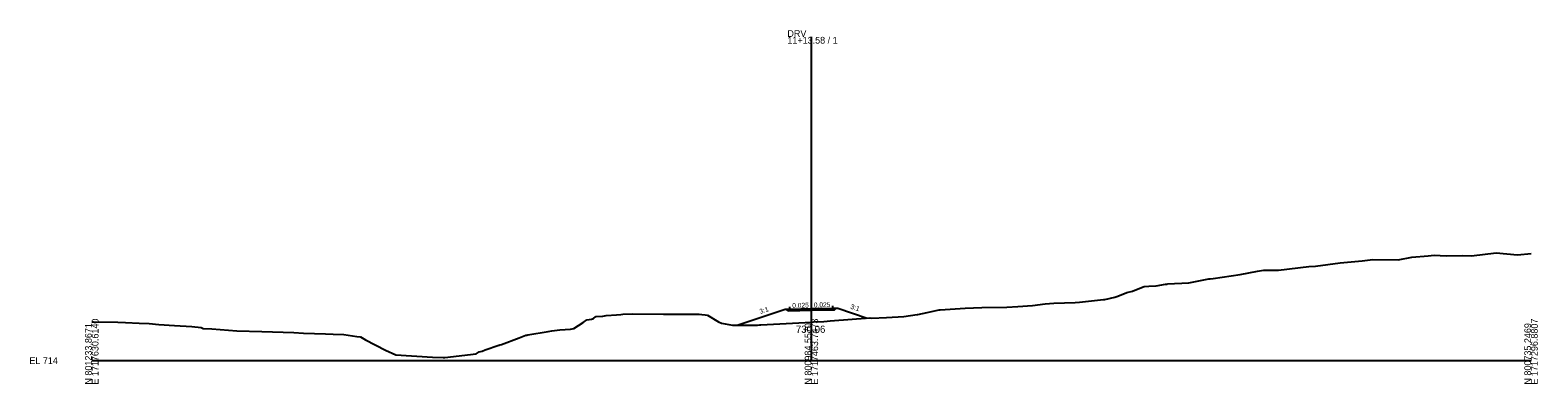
# Model space of a CAD drawing. Extents: x -26 to 603, y -10 to 3134.
# Drawn here: x -26 to 603, y 2490 to 2638 of the extents above; entities that cross this region are included whole.
import ezdxf

# ---------------------------------------------------------------- set-up
doc = ezdxf.new("R2010")
doc.units = 0
for name, color, linetype in [('Exist Cross Section Cell', 7, 'Continuous'), ('Exist XS Center Line Elevation Label', 7, 'Continuous'), ('Exist XS Ground Line', 7, 'Continuous'), ('Prop XS Dump Level', 7, 'Continuous'), ('Prop XS EOT Tick Mark', 7, 'Continuous'), ('Prop XS Finish Grade', 7, 'Continuous'), ('Prop XS Finish Grade Earthwork', 7, 'Continuous'), ('Prop XS Finish Grade Pavement', 7, 'Continuous'), ('Prop XS Pvmt Edge Slope', 7, 'Continuous'), ('Prop XS SE Text', 7, 'Continuous'), ('Prop XS Side Slope Text', 7, 'Continuous'), ('Prop XS Subgrade Earthwork', 7, 'Continuous')]:
    doc.layers.add(name, color=color, linetype=linetype)

msp = doc.modelspace()

# ---------------------------------------------------------------- linework, layer by layer
at = {"layer": 'Exist Cross Section Cell'}
for p, q in [((300, 2500), (300, 2634.89)), ((0, 2500), (300, 2500)), ((300, 2500), (600, 2500))]:
    msp.add_line(p, q, dxfattribs=at)
at = {"layer": 'Exist XS Ground Line'}
for p, q in [((507.41, 2539.22), (510.16, 2539.36)), ((510.16, 2539.36), (520.41, 2540.77)), ((520.41, 2540.77), (529.59, 2541.6)), ((529.59, 2541.6), (534, 2542.06)), ((534, 2542.06), (544.58, 2542)), ((544.58, 2542), (550.25, 2543.15)), ((550.25, 2543.15), (557.13, 2543.67)), ((557.13, 2543.67), (559.61, 2543.86)), ((559.61, 2543.86), (564.63, 2543.59)), ((564.63, 2543.59), (571.59, 2543.8)), ((571.59, 2543.8), (575.2, 2543.65)), ((575.2, 2543.65), (585.45, 2544.96)), ((585.45, 2544.96), (594.35, 2544.04)), ((594.35, 2544.04), (600, 2544.64)), ((457.39, 2532.36), (465.74, 2534.01)), ((465.74, 2534.01), (466.24, 2534.08)), ((466.24, 2534.08), (467.54, 2534.2)), ((467.54, 2534.2), (478.72, 2535.82)), ((478.72, 2535.82), (486, 2537.32)), ((486, 2537.32), (488.5, 2537.69)), ((488.5, 2537.69), (494.73, 2537.65)), ((494.73, 2537.65), (507.41, 2539.22)), ((426.47, 2526.43), (427.71, 2526.91)), ((427.71, 2526.91), (431.5, 2528.3)), ((431.5, 2528.3), (433.89, 2528.88)), ((433.89, 2528.88), (438.36, 2530.69)), ((438.36, 2530.69), (438.74, 2530.82)), ((438.74, 2530.82), (438.92, 2530.84)), ((438.92, 2530.84), (440.67, 2531.05)), ((440.67, 2531.05), (443.66, 2531.13)), ((443.66, 2531.13), (447.63, 2531.85)), ((447.63, 2531.85), (448.24, 2531.91)), ((448.24, 2531.91), (448.42, 2531.93)), ((448.42, 2531.93), (457.39, 2532.36)), ((348.21, 2520.05), (353.29, 2521.1)), ((353.29, 2521.1), (353.64, 2521.12)), ((353.64, 2521.12), (364.14, 2521.9)), ((364.14, 2521.9), (370.98, 2522.18)), ((370.98, 2522.18), (381.52, 2522.31)), ((381.52, 2522.31), (386.1, 2522.52)), ((386.1, 2522.52), (392.2, 2522.98)), ((392.2, 2522.98), (397.45, 2523.66)), ((397.45, 2523.66), (401.03, 2523.96)), ((401.03, 2523.96), (409.89, 2524.26)), ((409.89, 2524.26), (411.76, 2524.31)), ((411.76, 2524.31), (421.7, 2525.4)), ((421.7, 2525.4), (422.08, 2525.4)), ((422.08, 2525.4), (422.37, 2525.48)), ((422.37, 2525.48), (426.47, 2526.43)), ((0, 2516.11), (0.78, 2516.09)), ((0.78, 2516.09), (10.9, 2516.04)), ((10.9, 2516.04), (14, 2515.91)), ((14, 2515.91), (19.69, 2515.61)), ((19.69, 2515.61), (23.86, 2515.51)), ((23.86, 2515.51), (27.89, 2515.01)), ((27.89, 2515.01), (34.42, 2514.6)), ((34.42, 2514.6), (41.76, 2514.15)), ((41.76, 2514.15), (45.58, 2513.72)), ((200.92, 2513.42), (204.88, 2515.93)), ((204.88, 2515.93), (206.37, 2517.03)), ((206.37, 2517.03), (208.31, 2517.3)), ((208.31, 2517.3), (209.15, 2517.56)), ((209.15, 2517.56), (210.18, 2518.32)), ((210.18, 2518.32), (210.22, 2518.33)), ((210.22, 2518.33), (212.98, 2518.49)), ((212.98, 2518.49), (214.39, 2518.72)), ((214.39, 2518.72), (218.74, 2519.07)), ((218.74, 2519.07), (220.54, 2519.23)), ((220.54, 2519.23), (221.39, 2519.3)), ((221.39, 2519.3), (225.6, 2519.48)), ((225.6, 2519.48), (238.27, 2519.37)), ((238.27, 2519.37), (246.5, 2519.39)), ((246.5, 2519.39), (252.03, 2519.34)), ((252.03, 2519.34), (253.22, 2519.33)), ((253.22, 2519.33), (254.37, 2519.19)), ((254.37, 2519.19), (255.77, 2519.03)), ((255.77, 2519.03), (256.63, 2518.97)), ((256.63, 2518.97), (261.2, 2516.13)), ((261.2, 2516.13), (262.57, 2515.6)), ((262.57, 2515.6), (267.08, 2514.71)), ((267.08, 2514.71), (277.52, 2514.78)), ((277.52, 2514.78), (278.41, 2514.84)), ((278.41, 2514.84), (278.76, 2514.84)), ((278.76, 2514.84), (278.95, 2514.83)), ((278.95, 2514.83), (300, 2516.06)), ((300, 2516.06), (300.83, 2516.11)), ((300.83, 2516.11), (305.11, 2516.3)), ((305.11, 2516.3), (306.55, 2516.42)), ((306.55, 2516.42), (307.84, 2516.57)), ((307.84, 2516.57), (324.35, 2517.78)), ((324.35, 2517.78), (325.1, 2517.73)), ((325.1, 2517.73), (331.29, 2517.91)), ((331.29, 2517.91), (338.57, 2518.35)), ((338.57, 2518.35), (344.1, 2519.18)), ((344.1, 2519.18), (344.39, 2519.2)), ((344.39, 2519.2), (348.21, 2520.05)), ((45.58, 2513.72), (46.38, 2513.37)), ((46.38, 2513.37), (50.01, 2513.18)), ((50.01, 2513.18), (60.49, 2512.46)), ((60.49, 2512.46), (70.85, 2512.09)), ((70.85, 2512.09), (84.24, 2511.73)), ((84.24, 2511.73), (88.22, 2511.45)), ((88.22, 2511.45), (97.48, 2511.13)), ((97.48, 2511.13), (100.59, 2510.98)), ((100.59, 2510.98), (105.04, 2510.82)), ((105.04, 2510.82), (110.54, 2510.06)), ((110.54, 2510.06), (111.99, 2509.83)), ((111.99, 2509.83), (114.04, 2508.7)), ((114.04, 2508.7), (122.44, 2504.28)), ((170.83, 2506.75), (178.14, 2509.42)), ((178.14, 2509.42), (180.96, 2510.53)), ((180.96, 2510.53), (181.31, 2510.61)), ((181.31, 2510.61), (181.74, 2510.73)), ((181.74, 2510.73), (190.29, 2512.16)), ((190.29, 2512.16), (191.83, 2512.36)), ((191.83, 2512.36), (195.17, 2512.77)), ((195.17, 2512.77), (199.53, 2513.15)), ((199.53, 2513.15), (200.92, 2513.42)), ((122.44, 2504.28), (126.74, 2502.44)), ((126.74, 2502.44), (142.04, 2501.39)), ((147.21, 2501.32), (160.26, 2502.79)), ((160.26, 2502.79), (161.52, 2503.62)), ((161.52, 2503.62), (162.79, 2503.96)), ((162.79, 2503.96), (164.03, 2504.51)), ((164.03, 2504.51), (169.73, 2506.38)), ((169.73, 2506.38), (169.83, 2506.42)), ((169.83, 2506.42), (170.12, 2506.52)), ((170.12, 2506.52), (170.83, 2506.75)), ((142.04, 2501.39), (146.53, 2501.22)), ((146.53, 2501.22), (147.21, 2501.32))]:
    msp.add_line(p, q, dxfattribs=at)
at = {"layer": 'Prop XS Dump Level'}
for p, q in [((291, 2521.42), (300, 2521.65)), ((300, 2521.65), (309, 2521.87))]:
    msp.add_line(p, q, dxfattribs=at)
at = {"layer": 'Prop XS EOT Tick Mark'}
for p, q in [((291, 2521.42), (291, 2522.42)), ((309, 2521.87), (309, 2522.87))]:
    msp.add_line(p, q, dxfattribs=at)
at = {"layer": 'Prop XS Finish Grade'}
for p, q in [((291, 2521.42), (289.65, 2521.31)), ((309, 2521.87), (310.34, 2521.82))]:
    msp.add_line(p, q, dxfattribs=at)
at = {"layer": 'Prop XS Finish Grade Earthwork'}
for p, q in [((289, 2521.26), (269.4, 2514.73)), ((289.65, 2521.31), (289, 2521.26)), ((310.34, 2521.82), (311, 2521.8)), ((311, 2521.8), (323.29, 2517.7))]:
    msp.add_line(p, q, dxfattribs=at)
at = {"layer": 'Prop XS Finish Grade Pavement'}
for p, q in [((291, 2521.42), (300, 2521.65)), ((300, 2521.65), (309, 2521.87))]:
    msp.add_line(p, q, dxfattribs=at)
at = {"layer": 'Prop XS Pvmt Edge Slope'}
for p, q in [((291, 2521.42), (290.27, 2520.7)), ((309, 2521.87), (309.69, 2521.18))]:
    msp.add_line(p, q, dxfattribs=at)
at = {"layer": 'Prop XS Subgrade Earthwork'}
for p, q in [((290.27, 2520.7), (289.65, 2521.31)), ((290.27, 2520.7), (300, 2520.94)), ((300, 2520.94), (309.69, 2521.18)), ((309.69, 2521.18), (310.34, 2521.82))]:
    msp.add_line(p, q, dxfattribs=at)

# ---------------------------------------------------------------- texts
at = {"layer": 'Exist Cross Section Cell'}
for s, p in [('11+13.58 / 1', (290, 2632.09)), ('DRV', (290, 2634.89)), ('EL 714', (-26, 2498.6))]:
    msp.add_text(s, height=2.8, dxfattribs=at).set_placement(p)
for s, p in [('N 801233.8671', (0, 2490)), ('E 1717630.6140', (2.8, 2490)), ('N 800984.5570', (300, 2490)), ('E 1717463.7473', (302.8, 2490)), ('N 800735.2469', (600, 2490)), ('E 1717296.8807', (602.8, 2490))]:
    msp.add_text(s, height=2.8, rotation=90, dxfattribs=at).set_placement(p)
at = {"layer": 'Exist XS Center Line Elevation Label'}
msp.add_text('730.06', height=3, dxfattribs=at).set_placement((293.54, 2511.56))
at = {"layer": 'Prop XS Dump Level'}
for p in [(289, 2521.22), (311, 2521.76)]:
    msp.add_text('Case1', height=0.04, dxfattribs=at).set_placement(p)
at = {"layer": 'Prop XS SE Text'}
for p in [(292.02, 2521.95), (301.02, 2522.17)]:
    msp.add_text('0.025', height=2, rotation=1.42573, dxfattribs=at).set_placement(p)
at = {"layer": 'Prop XS Side Slope Text'}
for rotation, p in [(18.43495, (278.72, 2519.42)), (341.56505, (316.09, 2521.69))]:
    msp.add_text('3:1', height=2, rotation=rotation, dxfattribs=at).set_placement(p)

doc.saveas('drawing.dxf')
